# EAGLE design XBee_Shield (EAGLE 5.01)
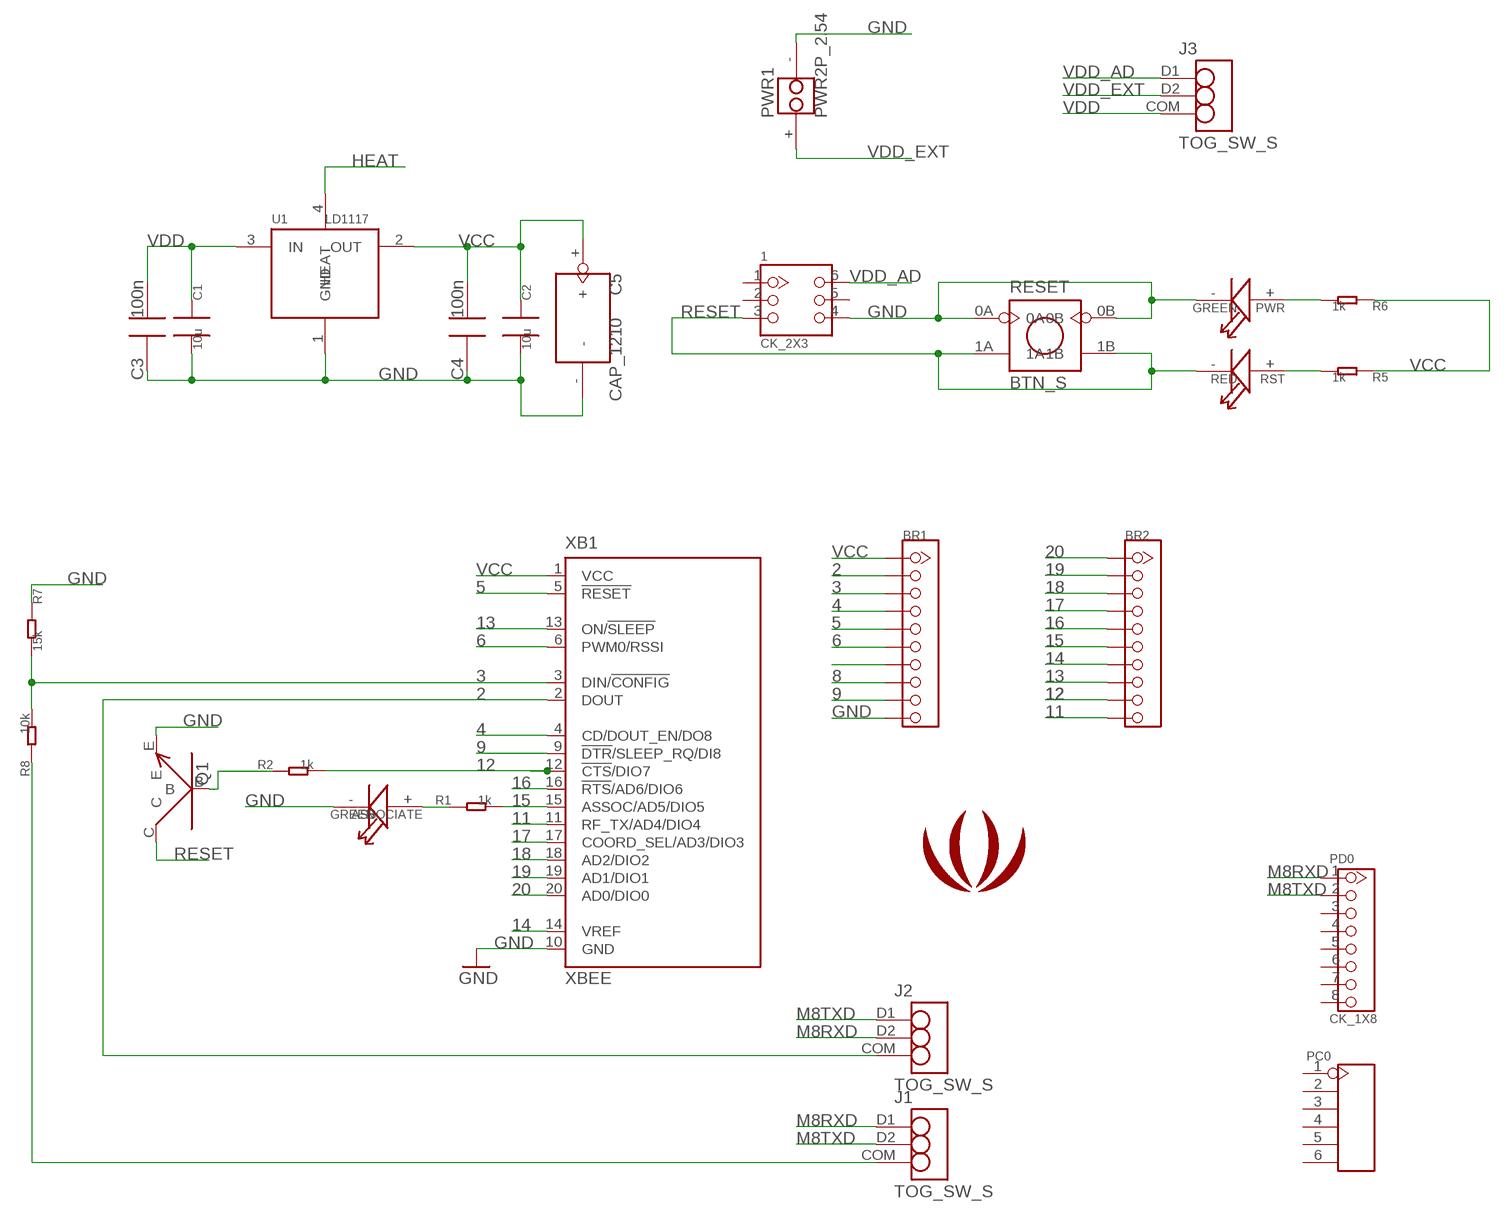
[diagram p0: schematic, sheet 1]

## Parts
1  CK_2X3  [CK_2X3]
ASSOCIATE  GREEN  LED0805  [LED0805]
BR1  CK1X10DD  [CK1X10]
BR2  CK1X10DD  [CK1X10]
C1  10u  C0805  [0805]
C2  10u  C0805  [0805]
C3  100n  C0603  [0603]
C4  100n  C0603  [0603]
C5  CAP_1210  [CAP_1210]
J1  TOG_SW_S  [TOG_SW_S]
J2  TOG_SW_S  [TOG_SW_S]
J3  TOG_SW_S  [TOG_SW_S]
PC0  CK_16  [CK_1*6]
PD0  CK_1X8  [CK_1X8]
PWR  GREEN  LED0805  [LED0805]
PWR1  PWR2P_2.54  [PWR2P_2.54]
Q1  NPN_9013  [SOT23]
R1  1k  R0603  [0603]
R2  1k  R0603  [0603]
R5  1k  R0603  [0603]
R6  1k  R0603  [0603]
R7  15k  R0603  [0603]
R8  10k  R0603  [0603]
RESET  BTN_S  [BTN_S]
RST  RED  LED0805  [LED0805]
U1  LD1117  [SOT223]
U$2  LOGO_COPPER150X124  [LOGO_COPPER_150X124]
XB1  XBEE  [XBEE]

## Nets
2: BR1.2 J2.COM XB1.2(DOUT)
3: BR1.3 R7.2 R8.2 XB1.3(DIN/!CONFIG)
4: BR1.4 XB1.4(CD/DOUT_EN/DO8)
5: BR1.5 XB1.5(!RESET)
6: BR1.6 XB1.6(PWM0/RSSI)
8: BR1.8
9: BR1.9 XB1.9(!DTR!/SLEEP_RQ/DI8)
11: BR2.10 XB1.11(RF_TX/AD4/DIO4)
12: BR2.9 R2.2 XB1.12(!CTS!/DIO7)
13: BR2.8 XB1.13(ON/!SLEEP)
14: BR2.7 XB1.14(VREF)
15: BR2.6 R1.2 XB1.15(ASSOC/AD5/DIO5)
16: BR2.5 XB1.16(!RTS!/AD6/DIO6)
17: BR2.4 XB1.17(COORD_SEL/AD3/DIO3)
18: BR2.3 XB1.18(AD2/DIO2)
19: BR2.2 XB1.19(AD1/DIO1)
20: BR2.1 XB1.20(AD0/DIO0)
GND [power]: 1.4 ASSOCIATE.- BR1.10 C1.2 C2.2 C3.1 C4.1 C5.- PWR1.- PWR.- Q1.E R7.1 RESET.0A RESET.0B U1.1(GND) XB1.10(GND)
HEAT: U1.4(HEAT)
M8RXD: J1.D1 J2.D2 PD0.1
M8TXD: J1.D2 J2.D1 PD0.2
N$1: ASSOCIATE.+ R1.1
N$2: PWR.+ R6.2
N$3: R5.2 RST.+
N$5: J1.COM R8.1
N$6: Q1.B R2.1
N$19: BR1.7
RESET: 1.3 Q1.C RESET.1A RESET.1B RST.-
VCC: BR1.1 C2.1 C4.2 C5.+ R5.1 R6.1 U1.2(OUT) XB1.1(VCC)
VDD [power]: C1.1 C3.2 J3.COM U1.3(IN)
VDD_AD [power]: 1.6 J3.D1
VDD_EXT [power]: J3.D2 PWR1.+
Unconnected: 1.1 1.2 1.5 PC0.1 PC0.2 PC0.3 PC0.4 PC0.5 PC0.6 PD0.3 PD0.4 PD0.5 PD0.6 PD0.7 PD0.8

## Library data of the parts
1 = CONNECTER:CK_2X3
ASSOCIATE PWR RST = CPT_SMD:LED0805
BR1 BR2 = CONNECTER:CK1X10
C1 C2 = CPT_SMD:C0805
C3 C4 = CPT_SMD:C0603; C0603: 100N
C5 = CPT_SMD:CAP_1210
J1-J3 = CPT_SMD:TOG_SW_S
PC0 = CONNECTER:CK_1*6
PD0 = CONNECTER:CK_1X8
PWR1 = CONNECTER:PWR2P_2.54
Q1 = CPT_SMD:NPN_9013
R1 R2 R5-R8 = CPT_SMD:R0603
RESET = CPT_SMD:BTN_S
U1 = ICs:LD1117
U$2 = logo:LOGO_COPPER
XB1 = EXT_moudle:XBEE: XBee (TM) /XBee-PRO(TM) OEM RF Modules Source: MaxStream, Inc. xbee_productmanual.pdf

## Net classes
0 default: clearance 0.203 mm
1 power: width 0.61 mm

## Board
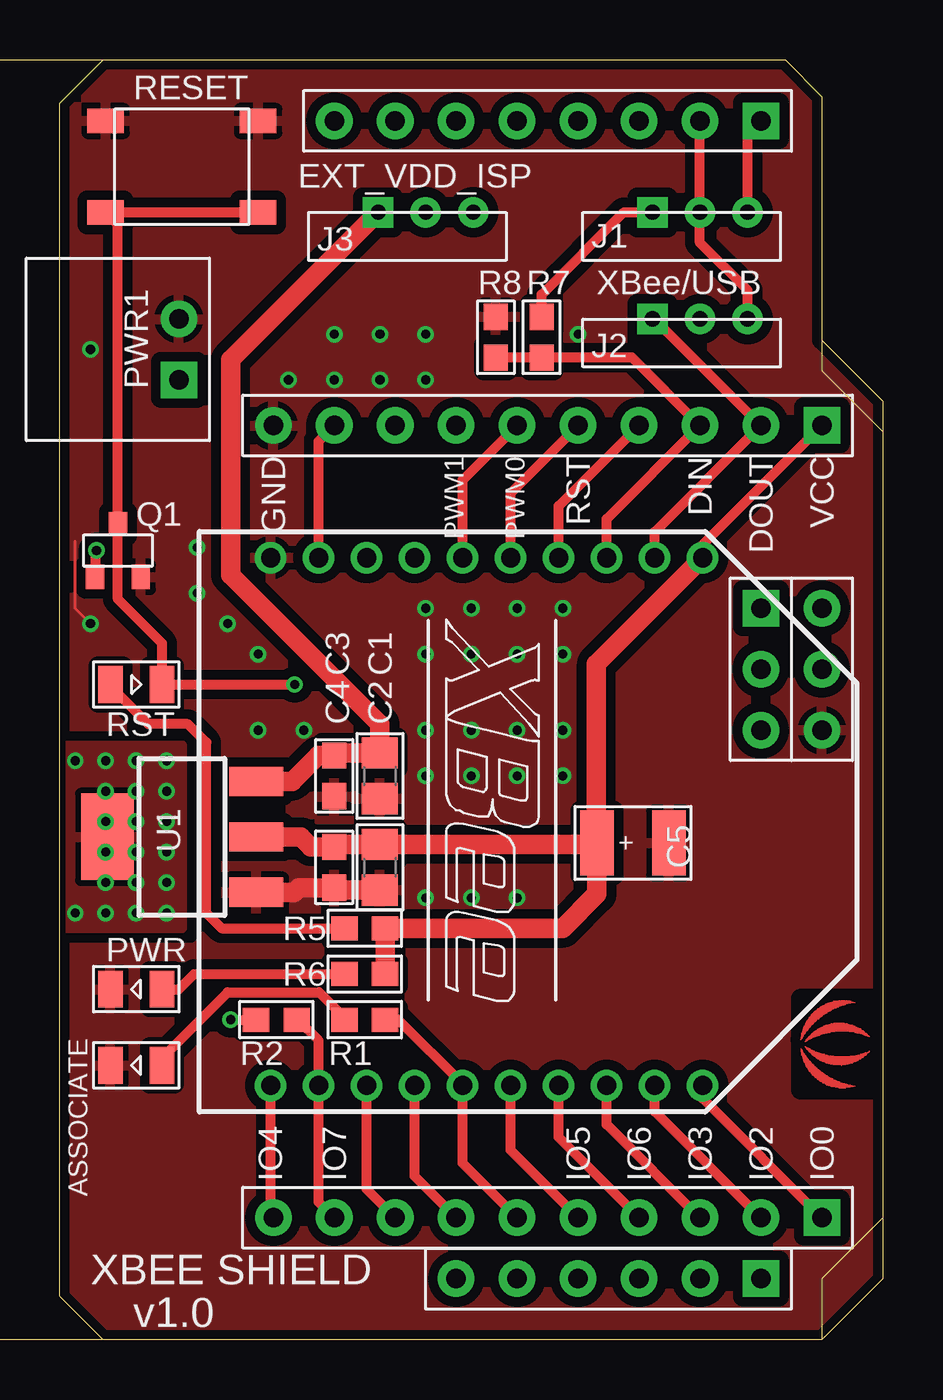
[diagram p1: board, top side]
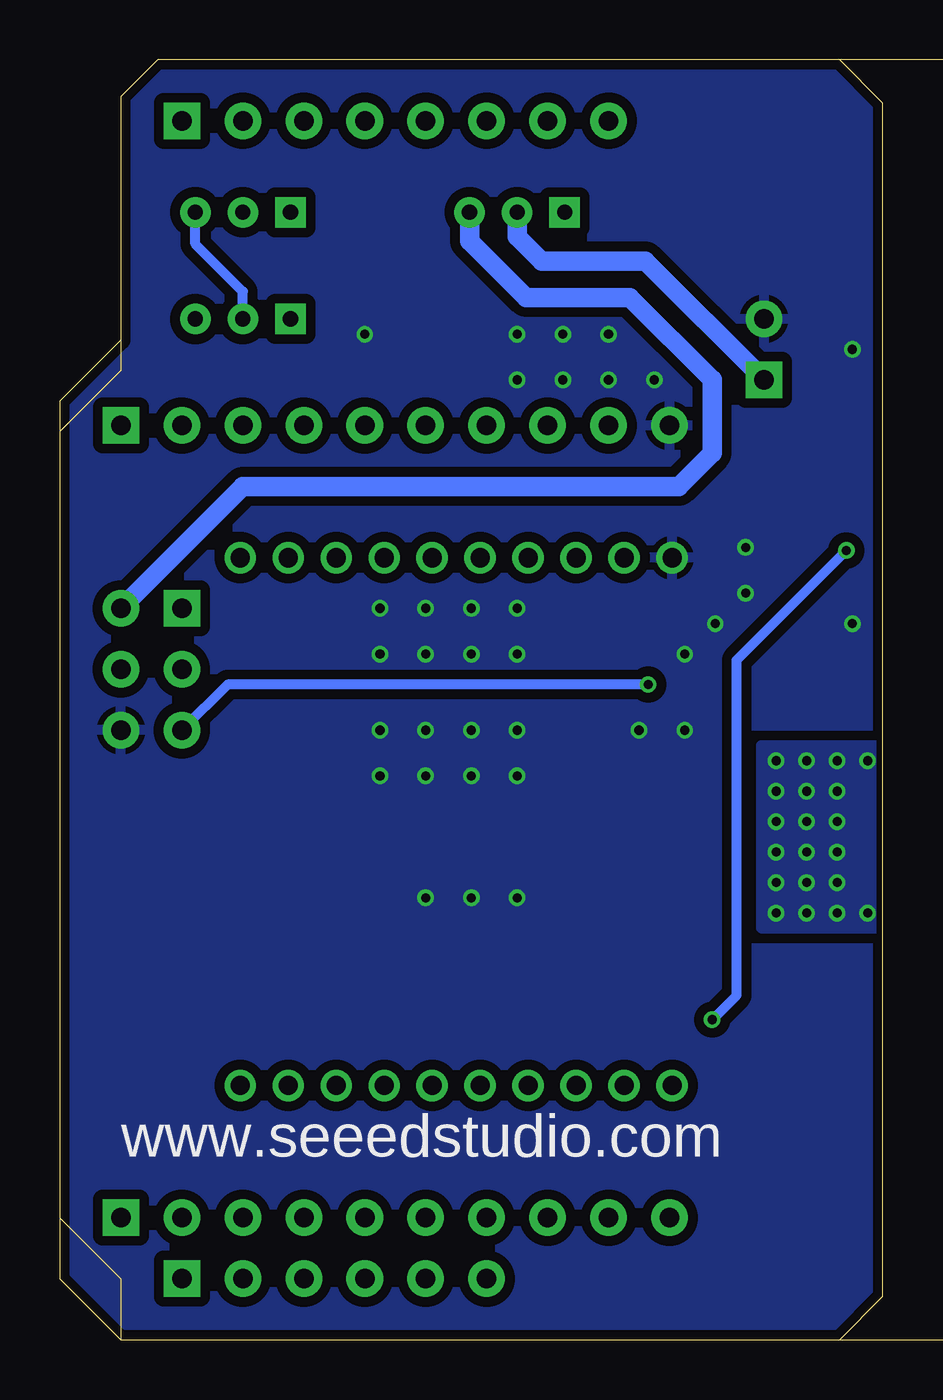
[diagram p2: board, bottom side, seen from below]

Size 34.29 x 53.34 mm. Coordinates in mm from the lower left corner, seen from the top.
Outline: 30.23,53.34 31.75,51.82 31.75,41.66 34.29,39.12 34.29,2.54 31.75,0 1.8,0 0,1.8 0,51.54 1.8,53.34 30.23,53.34
Copper layers (1*16): Top 0.035mm / dielectric 1.5mm / Bottom 0.035mm
Design rules "my rule_manufactory": minimum track width 0.1mm, minimum drill 0.3mm, track to track 6mil, track to pad 6mil, pad to pad 6mil, via to via 6mil, smd to smd 6mil, copper to edge 10mil, drill to drill 10mil, minimum pad ring 10mil, minimum via ring 6mil, stop-mask expansion 2mil, vias tented up to drill 100mil, thermal gap 10mil
tRestrict: area 30.9,10.4 to 33.8,14.2
Milling: 9 lines

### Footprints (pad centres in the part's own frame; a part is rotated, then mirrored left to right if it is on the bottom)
CK_2X3 = drill 0.813 pad 1.524 square: 1 -1.27,2.54 | drill 0.813 pad 1.524 round: 2 -1.27,0; 3 -1.27,-2.54; 4 1.27,-2.54; 5 1.27,0; 6 1.27,2.54
LED0805 = smd 1.016 x 1.524: + -1.077,0; - 1.077,0
CK1X10 = drill 0.813 pad 1.524 square: 1 0,11.43 | drill 0.813 pad 1.524 round: 2 0,8.89; 3 0,6.35; 4 0,3.81; 5 0,1.27; 6 0,-1.27; 7 0,-3.81; 8 0,-6.35; 9 0,-8.89; 10 0,-11.43
0805 = smd 1.3 x 1.5: 1 -0.95,0; 2 0.95,0
0603 = smd 1.1 x 1: 1 -0.85,0; 2 0.85,0
CAP_1210 = smd 1.4 x 2.7: + -1.5,0; - 1.5,0
TOG_SW_S = drill 0.635 pad 1.27 square: COM 0,-1.981 | drill 0.635 pad 1.27 round: D1 0,1.981; D2 0,0
CK_1*6 = drill 0.813 pad 1.524 square: 1 0,6.35 | drill 0.813 pad 1.524 round: 2 0,3.81; 3 0,1.27; 4 0,-1.27; 5 0,-3.81; 6 0,-6.35
CK_1X8 = drill 0.813 pad 1.524 square: 1 0,8.89 | drill 0.813 pad 1.524 round: 2 0,6.35; 3 0,3.81; 4 0,1.27; 5 0,-1.27; 6 0,-3.81; 7 0,-6.35; 8 0,-8.89
PWR2P_2.54 = drill 0.813 pad 1.524 square: + -1.27,0 | drill 0.813 pad 1.524 round: - 1.27,0
SOT23 = smd 0.762 x 1.016: B -0.95,-1.1; C 0,1.1; E 0.95,-1.1
BTN_S = smd 1.524 x 1.016: 0A -3.175,1.905; 0B 3.175,1.905; 1A -3.175,-1.905; 1B 3.175,-1.905
SOT223 = smd 1.219 x 2.235: 1 -2.311,-3.099; 2 0,-3.099; 3 2.311,-3.099 | smd 3.6 x 2.2: 4 0,3.099
XBEE = drill 0.8 pad 1.27 round: 1 -11,9; 2 -11,7; 3 -11,5; 4 -11,3; 5 -11,1; 6 -11,-1; 7 -11,-3; 8 -11,-5; 9 -11,-7; 10 -11,-9; 11 11,-9; 12 11,-7; 13 11,-5; 14 11,-3; 15 11,-1; 16 11,1; 17 11,3; 18 11,5; 19 11,7; 20 11,9

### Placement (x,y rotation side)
1  30.48,27.94 0 top
ASSOCIATE  3.17,11.43 180 top
BR1  20.32,38.1 270 top
BR2  20.32,5.08 270 top
C1  13.34,23.5 270 top
C2  13.34,19.68 270 top
C3  11.43,23.5 90 top
C4  11.43,19.68 90 top
C5  23.88,20.7 0 top
J1  26.67,46.99 270 top
J2  26.67,42.55 270 top
J3  15.24,46.99 270 top
PC0  22.86,2.54 270 top
PD0  20.32,50.8 270 top
PWR  3.17,14.61 180 top
PWR1  4.95,41.27 90 top
Q1  2.41,32.89 0 top
R1  12.7,13.34 0 top
R2  9.02,13.34 0 top
R5  12.7,17.14 180 top
R6  12.7,15.24 180 top
R7  18.16,41.78 270 top
R8  20.07,41.78 270 top
RESET  5.08,48.9 0 top
RST  3.17,27.3 0 top
U1  5.08,20.95 90 top
U$2  32,12.32 270 top
XB1  17.78,21.59 270 top

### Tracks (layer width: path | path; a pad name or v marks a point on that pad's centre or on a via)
2
  Top 0.406: XB1.2 24.78,33.67 BR1.2 24.77,42.55 J2.COM
3
  Top 0.406: R7.2 19.72,40.93 19.81,41.02 19.9,40.93 R8.2 23.84,40.93 BR1.3 22.78,34.21 XB1.3
4
  Top 0.406: XB1.4 20.78,34.75 BR1.4
5
  Top 0.406: XB1.5 18.78,35.29 BR1.5
6
  Top 0.406: XB1.6 16.78,35.83 BR1.6
9
  Top 0.406: XB1.9 10.78,37.45 BR1.9
11
  Top 0.406: XB1.11 8.78,5.19 BR2.10
12
  Top 0.406: BR2.9 10.78,5.73 XB1.12 10.78,12.46 9.91,13.34 R2.2
13
  Top 0.406: XB1.13 12.78,6.27 BR2.8
14
  Top 0.406: XB1.14 14.78,6.81 BR2.7
15
  Top 0.406: BR2.6 16.78,7.35 XB1.15 16.78,10.65 14.1,13.34 R1.2
16
  Top 0.406: XB1.16 18.78,7.89 BR2.5
17
  Top 0.406: XB1.17 20.78,8.43 BR2.4
18
  Top 0.406: XB1.18 22.78,8.97 BR2.3
19
  Top 0.406: XB1.19 24.78,9.51 BR2.2
20
  Top 0.406: XB1.20 26.78,10.05 BR2.1
GND  (via drill 0.38 pad 0.61)
  Top 0.076: v1.27,29.84 1.27,30.1
  Top 0.127: 0.63,33.27 0.63,30.48 v1.27,29.84
  Top 0.813: U1.1 9.75,18.64 9.95,18.84 C4.1 11.52,18.84 11.62,18.73 C2.2
  other vias: 19.05,18.41 17.14,18.41 10.16,25.4 8.25,25.4 8.25,28.57 6.98,29.84 5.71,31.11 5.71,33.02 20.95,23.5 19.05,23.5 17.14,23.5 15.24,23.5 15.24,25.4 17.14,25.4 19.05,25.4 20.95,25.4 20.95,28.57 19.05,28.57 17.14,28.57 15.24,28.57 15.24,30.48 17.14,30.48 19.05,30.48 20.95,30.48 15.24,40.01 13.34,40.01 11.43,40.01 9.52,40.01 11.43,41.91 13.34,41.91 15.24,41.91 21.59,41.91 15.24,18.41 1.27,41.27
  pour Top (isolate 0.406, rank 2): 31.75,42.55 34.29,40.01 34.29,2.54 31.75,0 1.8,0 0,1.8 0,51.54 1.8,53.34 31.75,53.34
  pour Bottom (isolate 0.406, rank 2): 31.75,42.55 34.29,40.01 34.29,2.54 31.75,0 1.8,0 0,1.8 0,51.54 1.8,53.34 31.75,53.34
HEAT  (via drill 0.38 pad 0.61)
  other vias: 0.63,24.13 1.91,24.13 3.17,24.13 4.45,24.13 4.45,22.86 3.17,22.86 1.91,22.86 1.91,21.59 3.17,21.59 4.45,21.59 4.45,20.32 3.17,20.32 1.91,20.32 1.91,19.05 3.17,19.05 4.45,19.05 4.45,17.78 3.17,17.78 1.91,17.78 0.63,17.78
  pour Top: 0,24.77 5.08,24.77 5.08,17.14 0,17.14
  pour Bottom (no thermals): 0,24.77 5.08,24.77 5.08,17.14 0,17.14
M8RXD
  Top 0.406: J1.D1 28.65,50.24 PD0.1
  Bottom 0.406: J1.D1 28.65,45.67 26.67,43.69 J2.D2
M8TXD
  Top 0.406: J2.D1 28.65,43.74 26.67,45.72 J1.D2 PD0.2
N$1
  Top 0.406: R1.1 11.85,13.42 10.79,14.48 6.98,14.48 4.25,11.74 ASSOCIATE.+
N$2
  Top 0.406: R6.2 5.59,15.24 4.95,14.61 PWR.+
N$3
  Top 0.406: R5.2 6.73,17.14 6.1,17.78 6.1,24.89 5.33,25.65 3.68,25.65 2.1,27.24 RST.+
N$5
  Top 0.406: J1.COM 23.49,46.99 20.07,43.56 R8.1
N$6  (via drill 0.38 pad 0.61)
  Top 0.406: v7.11,13.34 R2.1 | Q1.B 1.46,32.83 v1.52,32.89
  Bottom 0.406: v7.11,13.34 6.1,14.35 6.1,28.32 v1.52,32.89
RESET  (via drill 0.38 pad 0.61)
  Top 0.406: v9.78,27.3 RST.- 4.25,29.02 2.41,30.86 Q1.C 2.41,46.48 RESET.1A RESET.1B
  Bottom 0.406: 1.3 27.3,27.3 v9.78,27.3
VCC
  Top 0.406: XB1.1 26.78,33.13 BR1.1
  Top 0.813: U1.2 10.03,20.95 10.45,20.54 C4.2 11.43,20.57 11.49,20.64 C2.1 22.03,20.64 22.1,20.7 C5.+ | R6.1 13.55,16.85 13.59,16.89 13.55,16.93 R5.1 20.95,17.14 22.38,18.57 C5.+ | C5.+ 22.35,20.73 22.35,28.16 XB1.1
VDD
  Top 0.813: U1.3 9.68,23.27 10.76,24.34 C3.2 11.43,24.38 11.49,24.45 C1.1 13.34,25.65 7.11,31.88 7.11,40.84 J3.COM
VDD_AD
  Bottom 0.813: 1.6 26.67,35.56 8.51,35.56 7.11,36.96 7.11,40.01 10.54,43.43 14.86,43.43 17.22,45.8 J3.D1
VDD_EXT
  Bottom 0.813: PWR1.+ 9.91,44.96 14.22,44.96 15.24,45.97 J3.D2

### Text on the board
Top: top layer
Bottom: bottom layer
Dimension: boardoutline
tPlace: silktop | GND | PWM1 | PWM0 | RST | DOUT | VCC | IO4 | IO7 | IO5 | IO6 | IO3 | IO2 | IO0 | XBEE SHIELD | v1.0
bPlace: silkbottom | www.seeedstudio.com
tNames: EXT_VDD_ISP | XBee/USB | DIN
tStop: soldermask top
bStop: soldermask bottom
tCream: padmask top
bCream: padmask bottom
Drills: drill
